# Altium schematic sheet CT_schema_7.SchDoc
size 368 x 245 mm
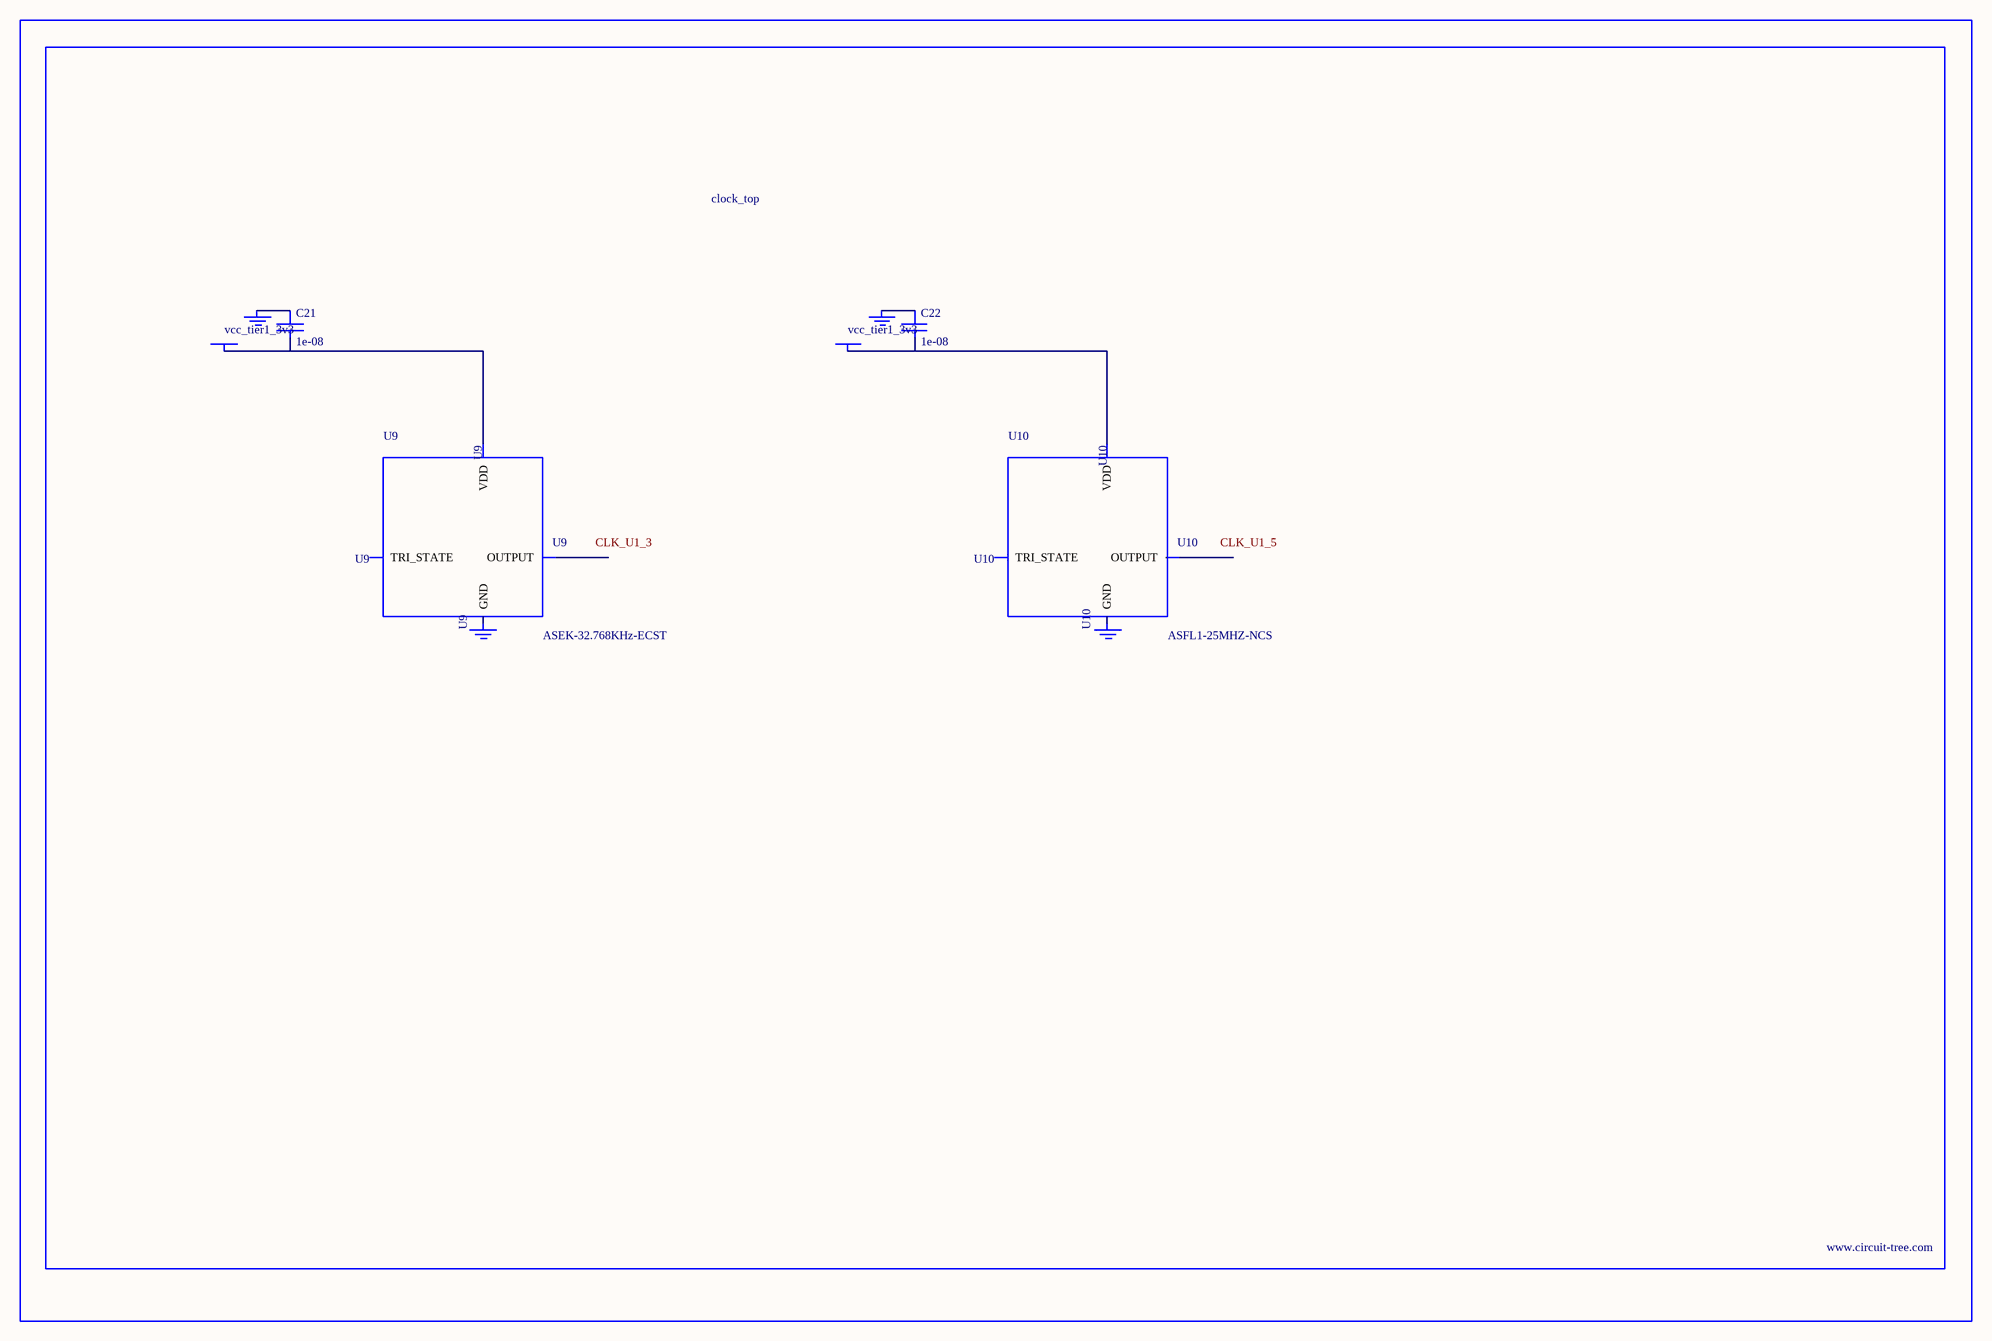
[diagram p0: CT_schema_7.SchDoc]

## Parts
BORDER6  (no value)
C21  1e-08  [C0402]
C22  1e-08  [C0402]
GND_INSTANCE_6_0  (no value)
GND_INSTANCE_6_1  (no value)
GND_INSTANCE_6_2  (no value)
GND_INSTANCE_6_3  (no value)
POWER_INSTANCE_6_0  vcc_tier1_3v3
POWER_INSTANCE_6_1  vcc_tier1_3v3
U9  ASEK-32.768KHz-ECST  [ASEK]
U10  ASFL1-25MHZ-NCS  [ASFL1]

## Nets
NetC21_1: C21.1 GND_INSTANCE_6_0.0(GND)
NetC21_2: C21.2 POWER_INSTANCE_6_0.0(PWR) U9.4(VDD)
NetC22_1: C22.1 GND_INSTANCE_6_2.0(GND)
NetC22_2: C22.2 POWER_INSTANCE_6_1.0(PWR) U10.4(VDD)

Not connected (* = marked no-connect by the designer): GND_INSTANCE_6_1 0(GND); GND_INSTANCE_6_3 0(GND); U9 1(TRI_STATE) 2(GND) 3(OUTPUT); U10 1(TRI_STATE) 2(GND) 3(OUTPUT)

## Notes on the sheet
- Labels drawn without touching a wire or pin: CLK_U1_3, CLK_U1_5

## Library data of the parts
BORDER6 = BORDER_PAGE6
C21 C22 = C0402C103K3RAC
GND_INSTANCE_6_0-GND_INSTANCE_6_3 = GND
POWER_INSTANCE_6_0 POWER_INSTANCE_6_1 = PWR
